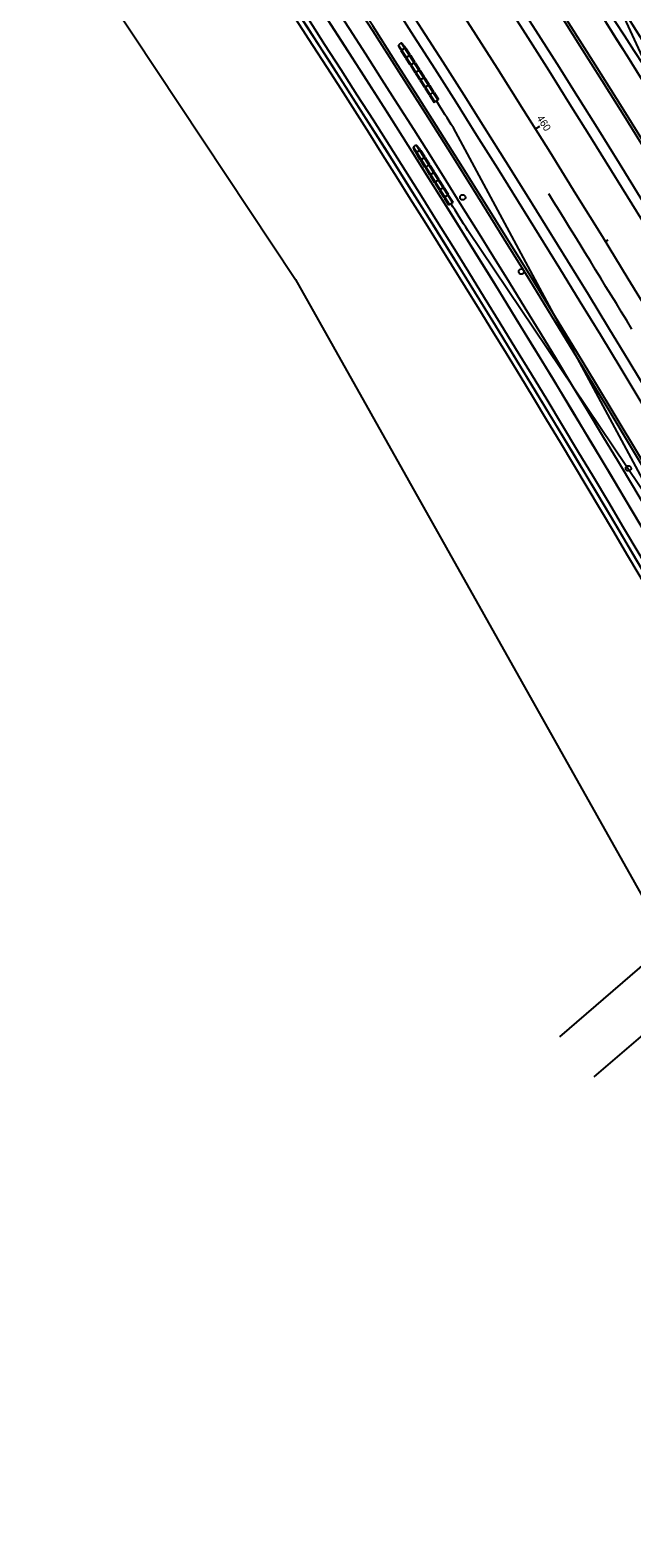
# Model space of a CAD drawing. Extents: x 7786 to 17579, y 337 to 8611.
# Drawn here: x 11209 to 11436, y 4573 to 5143 of the extents above; entities that cross this region are included whole.
import ezdxf

# ---------------------------------------------------------------- set-up
doc = ezdxf.new("R2010")
doc.units = 0
for name, color, linetype in [('GE_P_Alignment', 7, 'Continuous'), ('GE_P_Alignment_100_Stations', 7, 'Continuous'), ('HY_X_Water_Edge', 7, 'Continuous'), ('MT_P_Edge_Line', 7, 'Continuous'), ('MT_P_PCB', 7, 'Continuous'), ('MT_P_Text', 7, 'Continuous'), ('PM_X_Lane_Line', 7, 'Continuous'), ('PV_P_EOP', 7, 'Continuous'), ('PV_P_Shoulder', 7, 'Continuous'), ('PV_X_EOP', 7, 'Continuous'), ('PV_X_Shoulder', 7, 'Continuous'), ('RD_X_GR_Lt', 7, 'Continuous'), ('RD_X_GR_Rt', 7, 'Continuous'), ('RW_X_Esmt_LA', 7, 'Continuous')]:
    doc.layers.add(name, color=color, linetype=linetype)

msp = doc.modelspace()

# ---------------------------------------------------------------- linework, layer by layer
at = {"layer": 'GE_P_Alignment'}
msp.add_line((11244.05, 5559.32), (12302.66, 3255.22), dxfattribs=at)
msp.add_arc((6545.73, 2061.51), 5729.58, 24.676389, 48.6575, dxfattribs=at)
msp.add_arc((6545.73, 2061.51), 5729.58, 24.676389, 48.6575, dxfattribs=at)
at = {"layer": 'GE_P_Alignment_100_Stations'}
for p, q in [((11399.68, 5105.73), (11401.37, 5106.79)), ((11426.06, 5063.26), (11427.08, 5063.89)), ((11426.06, 5063.26), (11427.08, 5063.89))]:
    msp.add_line(p, q, dxfattribs=at)
at = {"layer": 'HY_X_Water_Edge'}
for p, q in [((11662.98, 4982.09), (11408.68, 4762.63)), ((11676.05, 4966.95), (11421.75, 4747.49))]:
    msp.add_line(p, q, dxfattribs=at)
at = {"layer": 'MT_P_Edge_Line'}
msp.add_circle((11394.34, 5051.82), 1, dxfattribs=at)
for radius, start, end in [(5698.58, 28.29546, 48.6575), (5760.58, 24.676389, 34.594405)]:
    msp.add_arc((6545.73, 2061.51), radius, start, end, dxfattribs=at)
at = {"layer": 'MT_P_PCB'}
for p, q in [((11354.75, 5099.51), (11368.28, 5077.9)), ((11355.86, 5098.37), (11354.85, 5099.51)), ((11354.16, 5097.3), (11353.58, 5098.71)), ((11367.15, 5077.19), (11353.62, 5098.8)), ((11354.4, 5096.94), (11354.16, 5097.3)), ((11354.63, 5096.88), (11354.4, 5096.94)), ((11354.57, 5096.65), (11354.63, 5096.88)), ((11356.16, 5094.11), (11354.57, 5096.65)), ((11354.63, 5096.88), (11356.04, 5097.77)), ((11355.86, 5098.37), (11356.09, 5098)), ((11356.04, 5097.77), (11356.09, 5098)), ((11356.27, 5097.71), (11356.04, 5097.77)), ((11356.39, 5094.06), (11356.16, 5094.11)), ((11356.27, 5097.71), (11357.86, 5095.17)), ((11356.34, 5093.83), (11356.39, 5094.06)), ((11357.93, 5091.28), (11356.34, 5093.83)), ((11356.39, 5094.06), (11357.81, 5094.94)), ((11357.81, 5094.94), (11357.86, 5095.17)), ((11358.04, 5094.89), (11357.81, 5094.94)), ((11358.04, 5094.89), (11359.63, 5092.35)), ((11358.16, 5091.23), (11357.93, 5091.28)), ((11358.11, 5091), (11358.16, 5091.23)), ((11358.11, 5091), (11359.7, 5088.46)), ((11358.16, 5091.23), (11359.57, 5092.12)), ((11359.57, 5092.12), (11359.63, 5092.35)), ((11359.8, 5092.06), (11359.57, 5092.12)), ((11359.93, 5088.41), (11359.7, 5088.46)), ((11359.8, 5092.06), (11361.4, 5089.52)), ((11359.88, 5088.18), (11359.93, 5088.41)), ((11359.88, 5088.18), (11361.47, 5085.63)), ((11359.93, 5088.41), (11361.34, 5089.29)), ((11361.34, 5089.29), (11361.4, 5089.52)), ((11361.57, 5089.24), (11361.34, 5089.29)), ((11361.57, 5089.24), (11363.16, 5086.69)), ((11361.7, 5085.58), (11361.47, 5085.63)), ((11361.65, 5085.35), (11361.7, 5085.58)), ((11361.65, 5085.35), (11363.24, 5082.81)), ((11361.7, 5085.58), (11363.11, 5086.46)), ((11363.11, 5086.46), (11363.16, 5086.69)), ((11363.34, 5086.41), (11363.11, 5086.46)), ((11363.47, 5082.76), (11363.24, 5082.81)), ((11363.34, 5086.41), (11364.93, 5083.87)), ((11363.41, 5082.53), (11363.47, 5082.76)), ((11363.41, 5082.53), (11365.01, 5079.98)), ((11363.47, 5082.76), (11364.88, 5083.64)), ((11364.88, 5083.64), (11364.93, 5083.87)), ((11365.11, 5083.59), (11364.88, 5083.64)), ((11365.11, 5083.59), (11366.7, 5081.04)), ((11365.24, 5079.93), (11365.01, 5079.98)), ((11365.18, 5079.7), (11365.24, 5079.93)), ((11365.18, 5079.7), (11366.86, 5077.02)), ((11365.24, 5079.93), (11366.65, 5080.81)), ((11366.65, 5080.81), (11366.7, 5081.04)), ((11366.88, 5080.76), (11366.65, 5080.81)), ((11366.86, 5077.02), (11368.56, 5078.08)), ((11366.88, 5080.76), (11368.56, 5078.08)), ((11474.41, 4917.93), (11374.11, 5067.39))]:
    msp.add_line(p, q, dxfattribs=at)
for centre, radius, start, end in [((11354.8, 5098.17), 1.34, 87.8676, 156.219), ((6558.16, 2041.07), 5687.88, 32.14506, 32.26594)]:
    msp.add_arc(centre, radius, start, end, dxfattribs=at)
at = {"layer": 'MT_P_Text'}
for p, q in [((11348.55, 5135.96), (11347.96, 5137.36)), ((11361.7, 5115.96), (11348, 5137.45)), ((11348.79, 5135.6), (11348.55, 5135.96)), ((11349.02, 5135.55), (11348.79, 5135.6)), ((11348.96, 5135.31), (11349.02, 5135.55)), ((11350.58, 5132.79), (11348.96, 5135.31)), ((11349.02, 5135.55), (11350.42, 5136.44)), ((11349.12, 5138.17), (11362.82, 5116.68)), ((11350.24, 5137.04), (11349.22, 5138.17)), ((11350.24, 5137.04), (11350.47, 5136.67)), ((11350.42, 5136.44), (11350.47, 5136.67)), ((11350.65, 5136.39), (11350.42, 5136.44)), ((11350.65, 5136.39), (11352.26, 5133.86)), ((11350.81, 5132.73), (11352.21, 5133.63)), ((11352.21, 5133.63), (11352.26, 5133.86)), ((11352.44, 5133.58), (11352.21, 5133.63)), ((11352.44, 5133.58), (11354.05, 5131.05)), ((11350.81, 5132.73), (11350.58, 5132.79)), ((11350.76, 5132.5), (11350.81, 5132.73)), ((11352.37, 5129.97), (11350.76, 5132.5)), ((11352.6, 5129.92), (11352.37, 5129.97)), ((11352.55, 5129.69), (11352.6, 5129.92)), ((11352.55, 5129.69), (11354.16, 5127.16)), ((11352.6, 5129.92), (11354, 5130.82)), ((11354, 5130.82), (11354.05, 5131.05)), ((11354.23, 5130.77), (11354, 5130.82)), ((11354.23, 5130.77), (11355.85, 5128.24)), ((11354.39, 5127.11), (11355.8, 5128.01)), ((11355.8, 5128.01), (11355.85, 5128.24)), ((11356.03, 5127.96), (11355.8, 5128.01)), ((11356.03, 5127.96), (11357.64, 5125.43)), ((11354.39, 5127.11), (11354.16, 5127.16)), ((11354.34, 5126.88), (11354.39, 5127.11)), ((11354.34, 5126.88), (11355.95, 5124.35)), ((11356.18, 5124.3), (11355.95, 5124.35)), ((11356.13, 5124.07), (11356.18, 5124.3)), ((11356.13, 5124.07), (11357.74, 5121.54)), ((11356.18, 5124.3), (11357.59, 5125.2)), ((11357.59, 5125.2), (11357.64, 5125.43)), ((11357.82, 5125.15), (11357.59, 5125.2)), ((11357.82, 5125.15), (11359.43, 5122.62)), ((11357.97, 5121.49), (11359.38, 5122.39)), ((11359.38, 5122.39), (11359.43, 5122.62)), ((11359.61, 5122.34), (11359.38, 5122.39)), ((11359.61, 5122.34), (11361.22, 5119.81)), ((11357.97, 5121.49), (11357.74, 5121.54)), ((11357.92, 5121.26), (11357.97, 5121.49)), ((11357.92, 5121.26), (11359.53, 5118.73)), ((11359.77, 5118.68), (11359.53, 5118.73)), ((11359.71, 5118.45), (11359.77, 5118.68)), ((11359.71, 5118.45), (11361.42, 5115.78)), ((11359.77, 5118.68), (11361.17, 5119.58)), ((11361.17, 5119.58), (11361.22, 5119.81)), ((11361.4, 5119.52), (11361.17, 5119.58)), ((11361.4, 5119.52), (11363.1, 5116.85)), ((11361.42, 5115.78), (11363.1, 5116.85)), ((11470.95, 4915.92), (11368.68, 5106.18))]:
    msp.add_line(p, q, dxfattribs=at)
for centre in [(11372.2, 5079.89), (11434.75, 4977.49)]:
    msp.add_circle(centre, 1, dxfattribs=at)
for centre, radius, start, end in [((6545.73, 2061.51), 5690.58, 28.34441, 35.6444), ((6545.73, 2061.51), 5679.58, 28.34441, 35.6444), ((6592.52, 1994.31), 5773.58, 31.053521, 35.256126), ((11349.18, 5136.83), 1.34, 88.3374, 156.6888), ((6546.17, 2060.81), 5703.58, 32.27206, 32.39261)]:
    msp.add_arc(centre, radius, start, end, dxfattribs=at)
at = {"layer": 'PM_X_Lane_Line'}
for radius, start in [(5761.58, 24.676389), (5697.58, 24.67639)]:
    msp.add_arc((6545.73, 2061.51), radius, start, 48.6575, dxfattribs=at)
at = {"layer": 'PV_P_EOP'}
for radius, start, end in [(5685.58, 29.60201, 47.0944), (5773.58, 29.790455, 34.494405)]:
    msp.add_arc((6545.73, 2061.51), radius, start, end, dxfattribs=at)
at = {"layer": 'PV_P_Shoulder'}
for radius, start, end in [(5677.58, 29.60201, 47.0944), (5781.58, 29.805871, 34.494405)]:
    msp.add_arc((6545.73, 2061.51), radius, start, end, dxfattribs=at)
at = {"layer": 'PV_X_EOP'}
for radius, start in [(5773.58, 29.790455), (5749.58, 29.743945), (5709.58, 29.66554), (5685.58, 29.61796)]:
    msp.add_arc((6545.73, 2061.51), radius, start, 48.6575, dxfattribs=at)
at = {"layer": 'PV_X_Shoulder'}
for radius, start in [(5781.58, 29.805871), (5745.58, 29.736155), (5713.58, 29.67343), (5677.58, 29.60201)]:
    msp.add_arc((6545.73, 2061.51), radius, start, 48.6575, dxfattribs=at)
at = {"layer": 'RD_X_GR_Lt'}
msp.add_arc((6545.73, 2061.51), 5720.83, 31.25934, 31.86026, dxfattribs=at)
at = {"layer": 'RD_X_GR_Rt'}
msp.add_arc((6545.73, 2061.51), 5675.58, 28.35494, 34.69774, dxfattribs=at)
at = {"layer": 'RW_X_Esmt_LA'}
msp.add_lwpolyline([(11037.71, 5458.09), (11309.03, 5048.88), (11665.76, 4413.91), (11802.46, 4096.06)], dxfattribs=at)

# ---------------------------------------------------------------- texts
at = {"layer": 'GE_P_Alignment_100_Stations'}
msp.add_text('460', height=2.8, rotation=302.0944, dxfattribs=at).set_placement((11400.01, 5109.89))

doc.saveas('drawing.dxf')
